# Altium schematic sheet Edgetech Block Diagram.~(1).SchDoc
size B
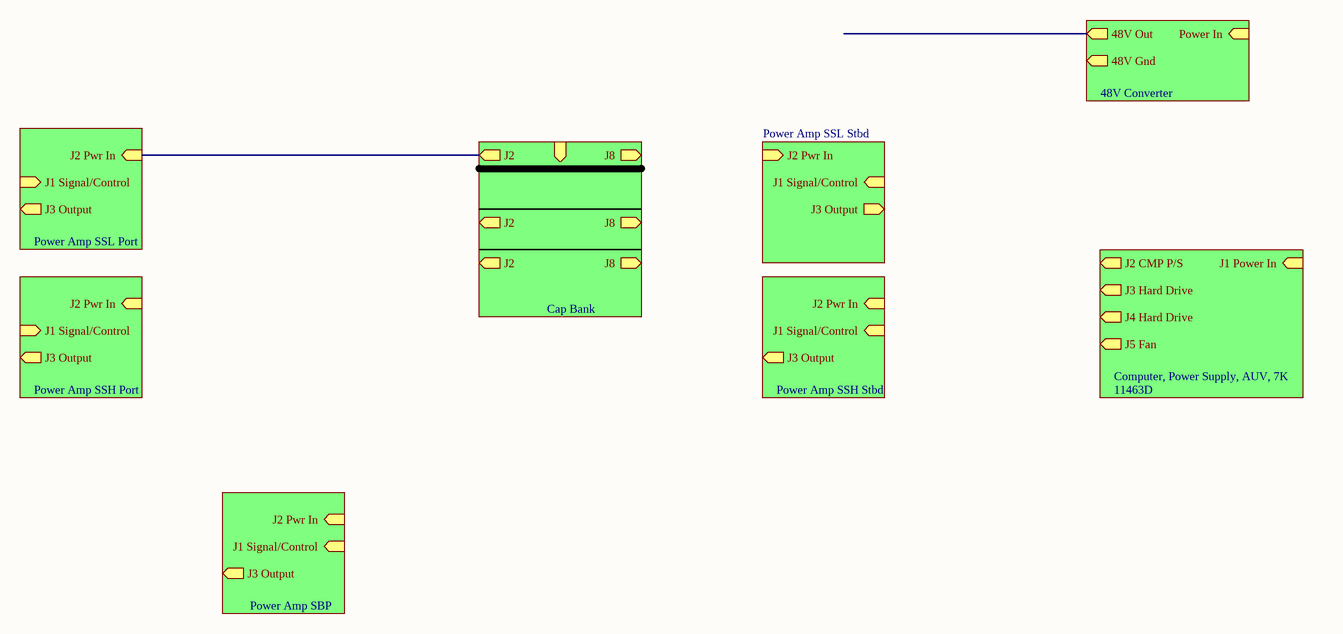
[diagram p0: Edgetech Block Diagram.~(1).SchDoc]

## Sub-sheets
48V Converter = File Name: Power In (in), 48V Out (out), 48V Gnd (out)
Cap Bank = File Name:  (in), J2 (out), J8 (out), J2 (out), J8 (out), J2 (out), J8 (out)
Computer, Power Supply, AUV, 7K = File Name: J1 Power In (in), J2 CMP P/S (out), J3 Hard Drive (out), J4 Hard Drive (out), J5 Fan (out)  | Part Number: 11463D
Power Amp SBP = File Name: J3 Output (out), J2 Pwr In (in), J1 Signal/Control (in)
Power Amp SSH Port = File Name: J3 Output (out), J2 Pwr In (in), J1 Signal/Control (in)
Power Amp SSH Stbd = File Name: J3 Output (out), J2 Pwr In (in), J1 Signal/Control (in)
Power Amp SSL Port = File Name: J3 Output (out), J2 Pwr In (in), J1 Signal/Control (in)
Power Amp SSL Stbd = File Name: J3 Output (out), J2 Pwr In (in), J1 Signal/Control (in)

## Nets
(unnamed): sheet Power Amp SSL Port/J2 Pwr In, sheet Cap Bank/J2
